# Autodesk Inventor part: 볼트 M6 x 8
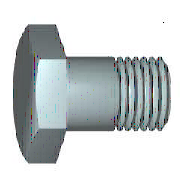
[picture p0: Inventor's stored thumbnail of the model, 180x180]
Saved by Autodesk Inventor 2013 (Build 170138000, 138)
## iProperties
Created: 2012-02
Part Number: 볼트 M6 x 8
Material: 강철, 연강
Description: 6각 머리 볼트 및 6각 머리 나사
Document SubType Name: Modeling
Standard: KS B 1002
Designer: mduedu
Standards Organization: KS
Language: ko-KR
Size Designation: C  M 6 x 12
Categories: <MemberInstance><Categories><Category DisplayName="조임쇠" InternalName="e4da775c-781d-43d5-af7c-5136215cf5a6" Mnemonic="FSTN"><Category DisplayName="볼트" InternalN
Density: 7.86 g/cm^3
Mass: 4.46616 g
Surface Area: 4.51243 cm^2
Volume: 0.568214 cm^3
IsCustomPart: 1
Author: mduedu
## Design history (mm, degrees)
sketch "스케치1"
  geometry: L1 (0, 3)-(8, 3); L2 (8, 3)-(8, 0); L3 (8, 0)-(0, 0); L4 (-2.4, 0)-(14.4, 0) reference; L5 (0, -0.6)-(0, 3.6) reference; L6 (0, 3)-(0, 0)
  constraints: 8 end point, 3 point on line, 1 collinear
  dimensions: "d2" = 6 diameter of L1 L3 (= GD); "d59" = 8 distance between parallel lines of L2 L5 (= NLG)
revolve "본체" sketch "스케치1" stored, may be unused: angle "d12" = 90 deg
sketch "스케치2"
  geometry: L1 (0, 5.774)-(5, 2.887); L2 (5, 2.887)-(5, -2.887); L3 (5, -2.887)-(0, -5.774); L4 (0, -5.774)-(-5, -2.887); L5 (-5, -2.887)-(-5, 2.887); L6 (-5, 2.887)-(0, 5.774); L7 (-7, 0)-(7, 0) reference; L8 (0, 8.083)-(0, -8.083) reference; 2 further points
  constraints: 12 end point, 2 midpoint, 1 coincident, 1 vertical, 11 other
  dimensions: "d11" = 10 distance between parallel lines of L5 L2 (= SW)
extrude "머리" join sketch "스케치2" distance "d3" = 4 (= KOH); taper "d4" = 0 deg
revolve "모따기1" stored, may be unused: angle "d21" = 90 deg
workplane "Work Plane1"
body "Solid1"
feature "스레드" dims "d15" = 9 (= GEL), "d16" = 0
chamfer "모따기2" distance "d6" = 0.61345 (= -0.5 x SPD + 0.5 x GD); stored, may be unused: second distance "d7" = 0.61355 (computed from GUL), angle "d55" = 45 deg
sketch "스케치4"
  geometry: L1 (-3.423, 6)-(-4, 5); L2 (-1.1, 0)-(-0.234, 0); L3 (-4.753, 0)-(0.519, 0) reference; L4 (-4, 6)-(-3.423, 6); L5 (-4, 5)-(-4, 6); L6 (0, 7.2)-(0, -1.2) reference
  constraints: 8 end point, 1 parallel, 1 perpendicular, 1 point on line
  dimensions: "d65" = 10 diameter of L1.end L2 (= SW); "d67" = 30 deg angle of L1 L5 (= ANG1); "d68" = 12 diameter of L4 L2 (= 1.2 x SW); "d69" = 4 distance between parallel lines of L5 L6 (= KOH)
other parameters: "NLG" = 8 [user parameter; used in 1 equation term], "GD" = 6 (= NND) [user parameter; used in 2 equation terms], "BDM" = 6 (= NND) [user parameter], "KOH" = 4 [user parameter; used in 2 equation terms], "GEL" = 9 [user parameter; used in 1 equation term], "SW" = 10 [user parameter; used in 5 equation terms], "SPD" = 4.7731 (= NND - 1.2269 x PTC) [user parameter; used in 1 equation term], "SD2" = 6 (= NND) [user parameter], "SD" = 0 [user parameter], "ANG1" = 30 deg [user parameter; used in 1 equation term], "GAL" = 0.61345 (= 0.61345 x PTC) [user parameter], "GUL" = 0.61345 (= 0.61345 x PTC) [user parameter; used in 1 equation term], "d8" = 0, "RR" = 0.25 [user parameter], "d58" = 0, "RR1" = 0.1 [user parameter], "GD1" = 4.7731 (= THREADDIA - 1.2269 x PTC) [user parameter], "THREADDIA" = 6 [user parameter; used in 1 equation term], "TOA" = 30 deg [user parameter], "PTC" = 1 [user parameter; used in 5 equation terms], "NND" = 6 [user parameter; used in 4 equation terms], "E0" = 11.55 (= 1.155 x SW) [user parameter]
